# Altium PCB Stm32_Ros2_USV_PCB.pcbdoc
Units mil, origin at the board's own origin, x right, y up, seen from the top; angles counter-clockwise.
Board outline 8440 x 7060 mil, 2 copper layers (Top Layer, Bottom Layer), stack 62.206 mil thick; 19 components, 25 nets, 105 pads, 37 vias.
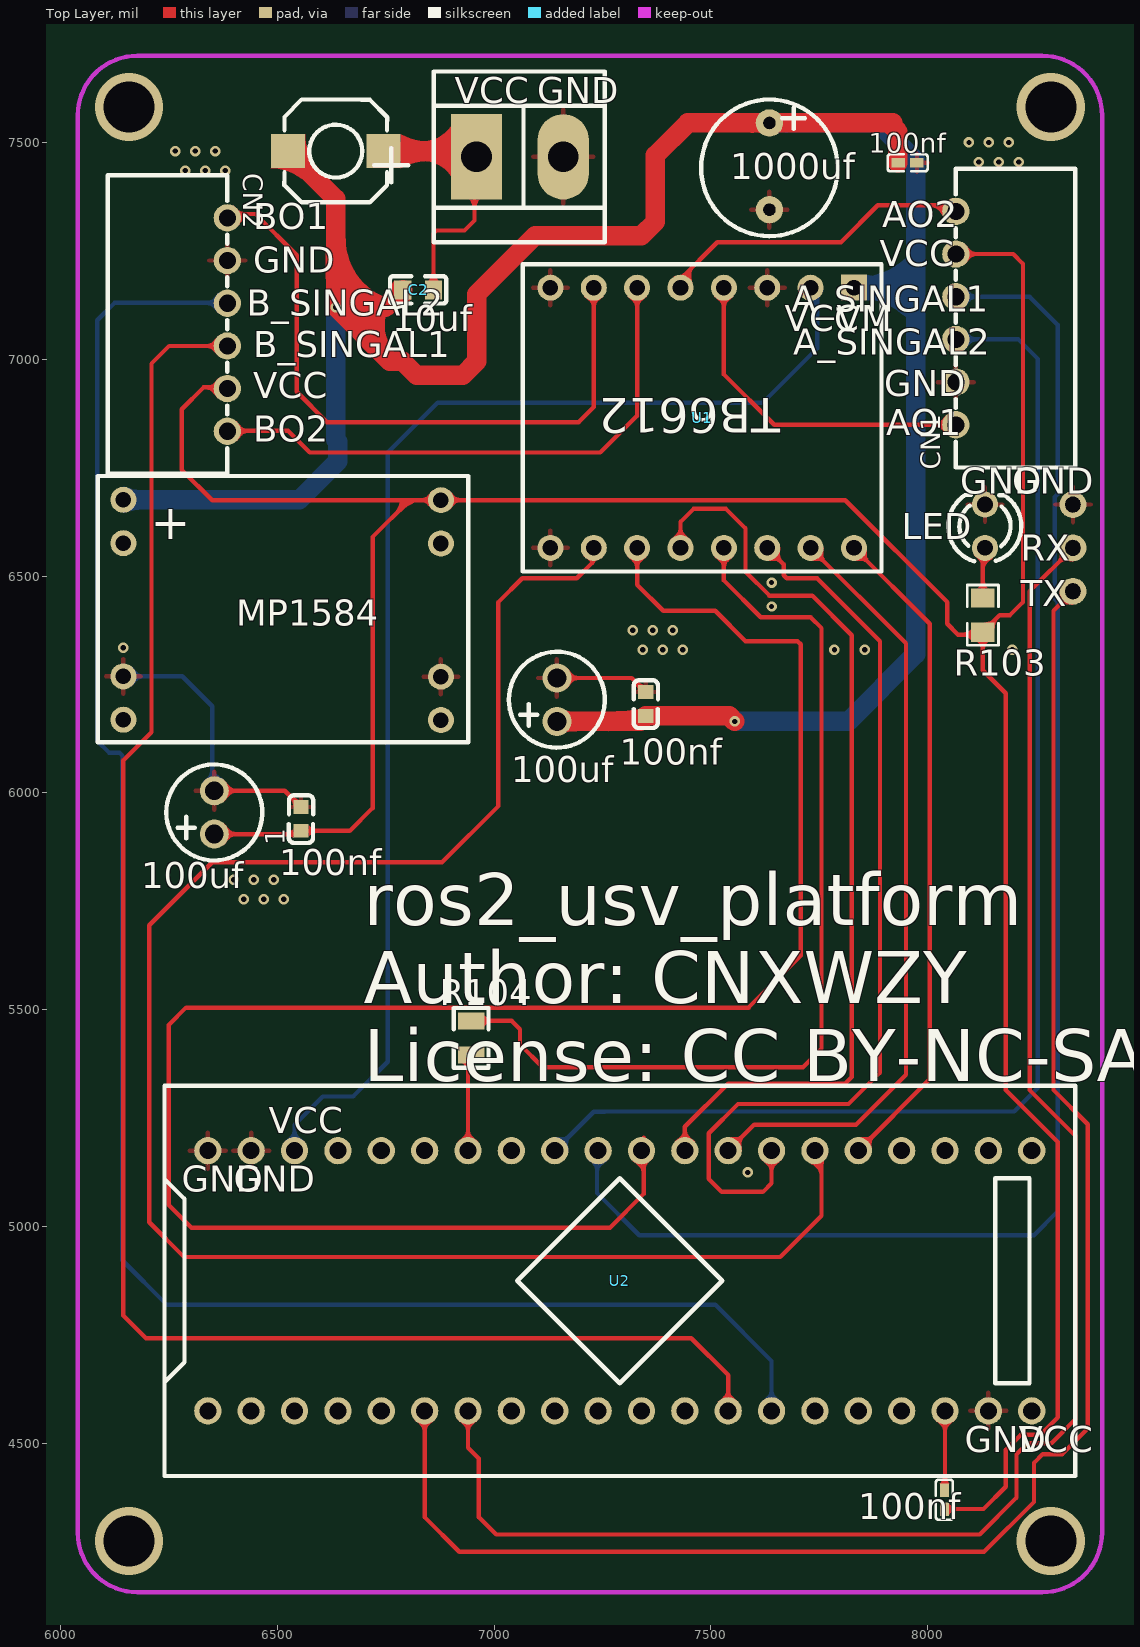
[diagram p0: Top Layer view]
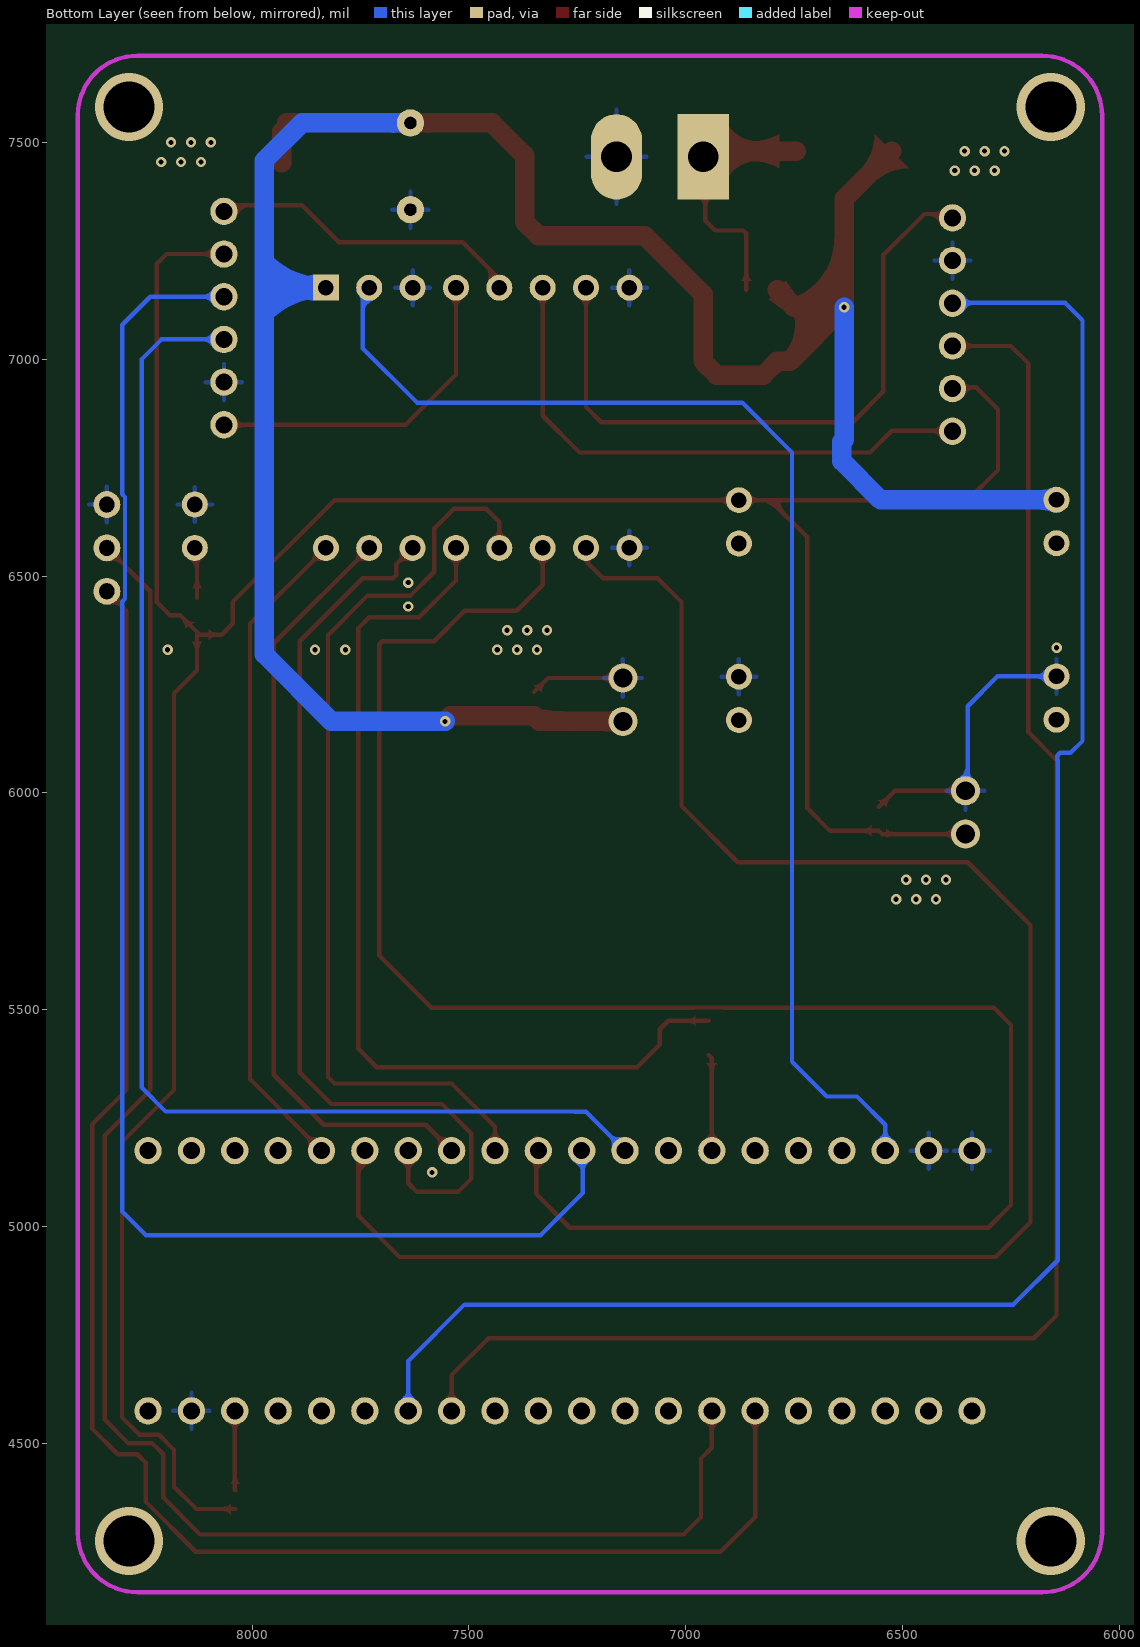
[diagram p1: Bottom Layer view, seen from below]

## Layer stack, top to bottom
Top Solder Mask Layer: solder mask 0.394, Dk 3.3
Top Layer: signal copper 1.379
Dielectric1: surface 59.449, FR4, Dk 4.5
Bottom Layer: signal copper 1.378
Bottom Solder Mask Layer: solder mask 0.394, Dk 3.3

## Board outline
11190,2750 2750,2750 2750,9810 11190,9810

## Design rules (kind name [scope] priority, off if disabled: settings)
BoardOutlineClearance copperThickness1oz [All] p0: genericclearance=10 ignorepadtopadclearanceinfootprint=FALSE except(0: Arc-SplitContinuation Track-SplitContinuation SMDPad-SplitContinuation THPad-SplitContinuation Via-SplitContinuation Fill-SplitContinuation Poly-SplitContinuation Region-SplitContinuation Text-SplitContinuation)
BoardOutlineClearance copperThickness2oz [All] p0: genericclearance=10 ignorepadtopadclearanceinfootprint=FALSE except(0: Arc-SplitContinuation Track-SplitContinuation SMDPad-SplitContinuation THPad-SplitContinuation Via-SplitContinuation Fill-SplitContinuation Poly-SplitContinuation Region-SplitContinuation Text-SplitContinuation)
BoardOutlineClearance otherClearance [All] p0: genericclearance=10 ignorepadtopadclearanceinfootprint=FALSE except(0: Arc-SplitContinuation Track-SplitContinuation SMDPad-SplitContinuation THPad-SplitContinuation Via-SplitContinuation Fill-SplitContinuation Poly-SplitContinuation Region-SplitContinuation Text-SplitContinuation)
Clearance copperThickness1oz [All] p1: gap=7 ignorepadtopadclearanceinfootprint=FALSE
Clearance copperThickness2oz [All] p1: gap=7 ignorepadtopadclearanceinfootprint=FALSE
Clearance otherClearance [All] p1: gap=7 ignorepadtopadclearanceinfootprint=FALSE
DiffPairsRouting differentialPair [All] p1: maxuncoupledlength=10 minlimit=6 maxlimit=Infinity mostfreqgap=6 toplayer_minwidth=5 toplayer_prefwidth=10 toplayer_maxwidth=100 bottomlayer_minwidth=5 bottomlayer_prefwidth=10 bottomlayer_maxwidth=100
PasteMaskExpansion pasteMaskExpansion [All] p1: expansion=0
PlaneConnect innerPlane [All] p1: planeconnectstyle=Relief reliefexpansion=20 reliefentries=4 reliefconductorwidth=10 reliefairgap=10
PolygonConnect copperRegion [All] p1: connectstyle=Relief reliefentries=4 reliefconductorwidth=10 polygonreliefangle="90 Angle" airgapwidth=10
RoutingVias viaSize [All] p1: viastyle="Through Hole" holewidth=12.0078 minholewidth=11.811 maxholewidth=248.0314 width=12.0078 minwidth=11.811 maxwidth=248.0314
SolderMaskExpansion solderMaskExpansion [All] p1: useseparateexpansions=TRUE expansion=2 expansionbottom=2
Width copperThickness1oz [All] p1: maxlimit=100 minlimit=5 preferedwidth=10
Width copperThickness2oz [All] p1: maxlimit=100 minlimit=8 preferedwidth=10

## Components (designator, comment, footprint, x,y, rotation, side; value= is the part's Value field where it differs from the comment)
1 "" C0603_7 6555,5940 r90 top locked
100nf "电容100nF" "电容100NF ±10% 16V" 7953.75,7451.69 r0 top
C2 "10UF-0603" 10UF-C0603 6825,7160 r180 top locked
CN1 "" CONN-TH_6P-P2.50_WAFER-XH2.54-6PWZ-R62 8065,7095 r90 top
CN2 "" CONN-TH_6P-P2.50_WAFER-XH2.54-6PWZ-R62 6385,7080 r270 top
U1 "TB6612FNG 最小开发板" TB6612FNG封装 7830,7165 r270 top locked
U2 "" CONN-TH_L53.3-W22.9_STM32F103C8T6-CARD 7290,4875 r0 top locked
? "" C0603_7 7350,6205 r90 top locked
? "3PIN_2.54MM_N3" 3PIN 8335,6565 r90 top locked
? "" R0805 8127.18,6410.14 r270 top locked
? "10KΩ" "电阻10KK COPY" 6947.18,5435.14 r90 top locked
? "MP1584降压模块" MP1584降压模块 6535,6420 r0 top locked
? "" 接线端子 7255,7270 r0 top locked
? "" SW-SMD_L6.0-W5.9-LS6.6 6635,7480 r180 top locked
? "" LED-TH_BD3.0-P2.54-FD 8132.18,6615.14 r90 top locked
? "100uF" 100UF电解电容 7150,6215 r90 top locked
? "100uF" 100UF电解电容 6360,5955 r90 top locked
? "1000uf" "电解电容1000UF/10V Φ3.5MM" 7635,7445 r90 top locked
? "电容100nF" "电容100NF ±10% 16V" 8040,4370 r90 top locked

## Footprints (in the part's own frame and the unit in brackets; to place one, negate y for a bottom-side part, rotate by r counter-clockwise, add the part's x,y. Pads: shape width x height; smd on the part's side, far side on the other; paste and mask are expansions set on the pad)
3PIN [mm]
  round 1.575 hole 0.889 slot 0.933 at 0 deg: 1(-2.54,0) 2(0,0) 3(2.54,0)
10UF-C0603 [mm]
  rect 1x1.1 smd: 1(-0.9,0) 2(0.9,0)
  silkscreen extent -1.65,-0.8 1.65,0.8
100UF电解电容 [mm]
  round 1.7 hole 1.1: 1(-1.27,0.127) 2(1.27,0.127)
  silkscreen extent -2.81,-2.68 2.81,2.94
C0603_7 [mm]
  rect 0.8x0.9 smd: 1(-0.7,0) 2(0.7,0)
  silkscreen extent -1.41,-0.71 1.39,0.72
CONN-TH_6P-P2.50_WAFER-XH2.54-6PWZ-R62 [mm]
  round 1.6 hole 1 copper offset 0,0: 1(-6.25,0) 2(-3.75,0) 3(-1.25,0) 4(1.25,0) 5(3.75,0) 6(6.25,0)
  silkscreen extent -8.75,-7 8.74,0
CONN-TH_L53.3-W22.9_STM32F103C8T6-CARD [mm]
  round 1.6 hole 1: 1(-24.13,-7.62) 2(-21.59,-7.62) 3(-19.05,-7.62) 4(-16.51,-7.62) 5(-13.97,-7.62) 6(-11.43,-7.62) 7(-8.89,-7.62) 8(-6.35,-7.62) 9(-3.81,-7.62) 10(-1.27,-7.62) 11(1.27,-7.62) 12(3.81,-7.62) 13(6.35,-7.62) 14(8.89,-7.62) 15(11.43,-7.62) 16(13.97,-7.62) 17(16.51,-7.62) 18(19.05,-7.62) 19(21.59,-7.62) 20(24.13,-7.62) 21(24.13,7.62) 22(21.59,7.62) 23(19.05,7.62) 24(16.51,7.62) 25(13.97,7.62) 26(11.43,7.62) 27(8.89,7.62) 28(6.35,7.62) 29(3.81,7.62) 30(1.27,7.62) 31(-1.27,7.62) 32(-3.81,7.62) 33(-6.35,7.62) 34(-8.89,7.62) 35(-11.43,7.62) 36(-13.97,7.62) 37(-16.51,7.62) 38(-19.05,7.62) 39(-21.59,7.62) 40(-24.13,7.62)
  silkscreen extent -26.67,-11.43 26.67,11.43
LED-TH_BD3.0-P2.54-FD [mil]
  round 60 hole 36: 1(-50,0) 2(50,0)
  silkscreen extent -81,-84 72,85
MP1584降压模块 [mil]
  round 60 hole 36: 1(-389.76,255.9) 2(-389.76,155.9) 3(-389.76,-151.18) 4(-389.76,-251.18) 5(342.52,255.12) 6(342.52,155.12) 7(342.52,-151.97) 8(342.52,-251.97)
  silkscreen extent -449,-303 406,311
R0805 [mm]
  rect 1.133x1.377 smd: 1(-1,0) 2(1,0)
  silkscreen extent -1.76,-0.92 1.76,0.92
SW-SMD_L6.0-W5.9-LS6.6 [mm]
  rect 2x2 smd: 1(-2.8,0) 2(2.8,0)
  silkscreen extent -3.02,-3.02 3.01,3
TB6612FNG封装 [mil]
  rect 60x60 hole 36: 1(0,0)
  round 60 hole 36: 2(0,-100) 3(0,-200) 4(0,-300) 5(0,-400) 6(0,-500) 7(0,-600) 8(0,-700) 9(600,-700) 10(600,-600) 11(600,-500) 12(600,-400) 13(600,-300) 14(600,-200) 15(600,-100) 16(600,0)
  silkscreen extent -54,-763 654,63
接线端子 [mm]
  rect 3x5 hole 1.8: 1(-7.5,5)
  oval 3x5 hole 1.8: 2(-2.42,5)
  silkscreen extent -13.5,0 0,10
"电容100NF ±10% 16V" [mm]
  rect 0.79x0.54 smd: 1(-0.545,0.035) 2(0.545,0.035)
  silkscreen extent -1.17,-0.46 1.17,0.53
"电解电容1000UF/10V Φ3.5MM" [mm]
  round 1.6 hole 0.711 slot 0.716 at 0 deg: 1(2.54,0) 2(-2.54,0)
  silkscreen extent -4.09,-4 3.91,4
"电阻10KK COPY" [mm]
  rect 1x1.55 smd: 1(-1,0) 2(1,0)
  silkscreen extent -1.75,-1.02 1.75,1.02

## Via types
v1: diameter 24, hole 12.01, Top Layer to Bottom Layer, 31 vias
v2: diameter 157.48, hole 118.11, Top Layer to Bottom Layer, 4 vias
v3: diameter 24.02, hole 12.01, Top Layer to Bottom Layer, 2 vias

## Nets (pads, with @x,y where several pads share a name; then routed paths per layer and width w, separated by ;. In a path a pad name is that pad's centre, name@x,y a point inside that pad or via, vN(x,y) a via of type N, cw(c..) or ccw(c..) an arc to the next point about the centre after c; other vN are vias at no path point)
$1N61: ?.1@6745.24,7480.01 ?.1@6959.72,7466.85 C2.1 | length 605.7
  Top Layer w10: C2.1 6860.44,7290 6867.51,7297.07 6932.07,7297.07 6955,7320 6955,7462.13 ?.1@6959.72,7466.85
  Top Layer w45: ?.1@6745.24,7480.01 6946.57,7480.01 ?.1@6959.72,7466.85
$1N63: ?.1@8127.18,6449.51 ?.1@8132.18,6565.14 | length 117.7
  Top Layer w10: ?.1@8127.18,6449.51 8127.18,6560.14 ?.1@8132.18,6565.14
$1N81: ?.2@6947.18,5474.51 U1.13 | length 2205.8
  Top Layer w10: ?.2@6947.18,5474.51 7040.49,5474.51 7060,5455 7060,5420 7112.5,5367.5 7712.5,5367.5 7755,5410 7755,6380 7730,6405 7615,6405 7530,6490 U1.13
$1N88: ?.2@8038.63,4391.47 U2.18 | length 184.1
  Top Layer w10: ?.2@8038.63,4391.47 8040,4392.84 U2.18
A_SINGAL1: CN1.4 U2.31 | length 3535.5
  Bottom Layer w10: U2.31 7237.5,5172.5 7237.5,5077.5 7335,4980 8245,4980 8299.61,5034.61 8299.61,6441.01 8293.01,6447.61 8293.01,6682.39 8299.61,6688.99 8299.61,7079.61 8235,7144.22 CN1.4
A_SINGAL2: CN1.3 U2.32 | length 3062.9
  Bottom Layer w10: U2.32 7230,5265 7255,5265 7255.4,5265.4 8199.6,5265.4 8254.19,5320 8254.19,7000.81 8209.2,7045.8 CN1.3
AIN1: U1.14 U2.27 | length 2157.4
  Top Layer w10: U1.14 7667.93,6527.07 7667.93,6502.07 7675,6495 7745,6495 7890,6350 7890,5355 7817.5,5282.5 7562.5,5282.5 7495,5215 7495,5110 7525,5080 7620,5080 7640,5100 U2.27
AIN2: U1.15 U2.28 | length 1788.6
  Top Layer w10: U2.28 7599.72,5234.72 7834.72,5234.72 7950,5350 7950,6345 U1.15
AO1: CN1.1 U1.4 | length 783.1
  Top Layer w10: U1.4 7530,6965 7646.06,6848.94 CN1.1
AO2: CN1.6 U1.5 | length 731.2
  Top Layer w10: U1.5 7430,7185 7515,7270 7800,7270 7885,7355 8051.06,7355 CN1.6@8065,7341.06
B_SINGAL1: CN2.4 U2.13 | length 3948.3
  Top Layer w10: CN2.4 6250.78,7030.78 6210,6990 6210,6140 6145,6075 6145,4795 6197.5,4742.5 7455,4742.5 7540,4657.5 U2.13
B_SINGAL2: CN2.3 U2.14 | length 4231.9
  Bottom Layer w10: CN2.3 6384.2,7130 6125,7130 6085,7090 6085,6120 6112.08,6092.92 6136.28,6092.92 6143.35,6085.85 6143.35,6075.85 6142.5,6075 6142.5,4922.5 6245,4820 7510,4820 7640,4690 U2.14
BIN1: U1.12 U2.29 | length 2153
  Top Layer w10: U1.12 7430,6625 7460,6655 7535,6655 7580,6610 7580,6510 7635,6455 7733.77,6455 7825,6363.77 7825,5345 7810,5330 7540,5330 7440,5230 U2.29
BIN2: U1.11 U2.30 | length 4454.1
  Top Layer w10: U1.11 7330,6480 7390,6420 7510,6420 7580,6350 7700,6350 7707.07,6342.93 7707.07,5625 7587.07,5505 6982.42,5505 6982.24,5505.18 6912.11,5505.18 6911.94,5505 6290,5505 6250,5465 6250,5050 6302.5,4997.5 7267.5,4997.5 7345,5075 U2.30@7345,5205
BO1: CN2.1 U1.7 | length 1492.8
  Top Layer w10: CN2.1@6410.06,7335.15 6449.85,7335.15 6545,7240 6545,6925 6615,6855 7195,6855 7230,6890 U1.7
BO2: CN2.6 U1.6 | length 1270.9
  Top Layer w10: CN2.6@6410.06,6835.15 6524.85,6835.15 6575,6785 7245,6785 7330,6870 U1.6
GND: 1.2 100nf.2 ?.2@6355,6005 ?.2@7145,6265 ?.2@7159.72,7466.85 ?.2@7350,6232.56 ?.2@7635,7345 ?.2@8132.18,6665.14 ?.3 ?.7 CN1.2 CN2.2 U1.3 U1.8 U1.9 U2.19 U2.39 U2.40 | length 864.3
  Top Layer w10: ?.2@6355,6005 6517.56,6005 1.2 ; ?.2@7145,6265 7317.56,6265 ?.2@7350,6232.56
  Bottom Layer w10: ?.3@6145.24,6268.82 6281.18,6268.82 6350,6200 6350,6010 ?.2@6355,6005
  other v1: 7585,5125 6423,5755 6469,5755 6515,5755 6400,5800 6446,5800 6492,5800 7343,6330 7389,6330 7435,6330 7785,6330 7855,6330 8195,6330 6145,6335 7320,6375 7366,6375 7412,6375 7640,6430 7640,6485 6288,7435 6334,7435 6380,7435 8118,7455 8164,7455 8210,7455 6265,7480 6311,7480 6357,7480 8095,7500 8141,7500 8187,7500
PWMA: U1.16 U2.25 | length 1530.8
  Top Layer w10: U1.16 8005,6390 8005,5340 U2.25
PWMB: U1.10 U2.26 | length 4142.5
  Top Layer w10: U1.10 7227.07,6562.07 7227.07,6531.09 7190.98,6495 7065,6495 7010,6440 7010,5970 6880,5840 6350,5840 6205,5695 6205,5010 6285,4930 7660,4930 7755,5025 7755,5160 U2.26
RX: ?.2@8335,6565 U2.7 | length 3910.2
  Top Layer w10: U2.7 6940,4490 6965,4465 6965,4330 7005,4290 8120,4290 8205,4375 8205,4475 8230,4500 8285,4500 8340,4555 8340,5210 8235,5315 8235,6465 ?.2@8335,6565
STBY: ?.1@6947.18,5395.77 U2.34 | length 223.7
  Top Layer w10: U2.34 6940,5388.6 ?.1@6947.18,5395.77
TX: ?.1@8335,6465 U2.6 | length 3959.9
  Top Layer w10: U2.6 6840,4330 6920,4250 8130,4250 8245,4365 8245,4455 8265,4475 8310,4475 8369.04,4534.04 8369.04,5235.96 8290,5315 8290,6420 ?.1@8335,6465
VCC+3.3V: U1.2 U2.38 | length 2975.7
  Bottom Layer w10: U2.38 6540,5235 6605,5300 6675,5300 6755,5380 6755,6785 6870,6900 7620,6900 7745,7025 7745,7150 U1.2
VCC+5V: 1.1 ?.1@6355,5905 ?.1@8038.63,4348.55 ?.2@8127.18,6370.77 ?.5 CN1.5 CN2.5 | length 6759.1
  Top Layer w10: ?.1@6355,5905 6547.56,5905 1.1 6667.44,5912.44 6720,5965 6720,6590 6805,6675 ; CN2.5@6359.94,6935.15 6330.15,6935.15 6280,6885 6280,6745 6350,6675 6805,6675 ; ?.1@8038.63,4348.55 8128.55,4348.55 8180,4400 8180,4485 8215,4520 8260,4520 8300,4560 8300,5195 8180,5315 8180,6230 8127.18,6282.82 ?.2@8127.18,6370.77 ; CN1.5 8197.36,7242.64 8220,7220 8220,6440 8190,6410 8166.41,6410 ?.2@8127.18,6370.77 ; 6805,6675 6877.4,6675 ?.5 7809.88,6675.12 8045,6440 8045,6390 8070,6365 8121.41,6365 ?.2@8127.18,6370.77
VCC+12V: 100nf.1 ?.1@6145.24,6675.9 ?.1@7145,6165 ?.1@7350,6177.44 ?.1@7635,7545 ?.2@6524.76,7480.01 C2.2 U1.1 | length 5892.9
  Top Layer w45: ?.2@6524.76,7480.01 6635,7369.77 v3(6635,7120) ; C2.2 6749.56,7120 v3(6635,7120) ; ?.1@7145,6165 7337.56,6165 7350,6177.44 7542.56,6177.44 v3(7555,6165) ; 7920,7545 7911.03,7545 ; 100nf.1@7931.18,7453.06 7931.18,7524.85 7911.03,7545 ; v3(6635,7120) 6760,6995 6789.56,6995 6821.38,6963.18 6928.18,6963.18 6960,6995 6960,7150 7095,7285 7340,7285 7371.82,7316.82 7371.82,7470 7446.82,7545 7635,7545 7911.03,7545
  Bottom Layer w45: ?.1@6145.24,6675.9 6550.9,6675.9 6640,6765 6640,6810 6635,6815 v3(6635,7120) ; v3(7555,6165) 7817.06,6165 7972.06,6320 7972.06,7167.19 ; ?.1@7635,7545 7885,7545 7972.06,7457.94 7972.06,7167.19 ; U1.1 7969.87,7165 7972.06,7167.19
pads on no net: ?.2@6145.24,6575.9 ?.4 ?.6 ?.8 U2.1 U2.2 U2.3 U2.4 U2.5 U2.8 U2.9 U2.10 U2.11 U2.12 U2.15 U2.16 U2.17 U2.20 U2.21 U2.22 U2.23 U2.24 U2.33 U2.35 U2.36 U2.37
copper on no net:
  other v2: 6158.11,4274.79 8284.09,4274.8 6158.11,7581.89 8284.09,7581.89

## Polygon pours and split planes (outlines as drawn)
GND on Top Layer (solid, remove dead copper, pour order 0): 5595,8120 9140,8120 9140,3935 5595,3935
GND on Bottom Layer (solid, remove dead copper, pour order 4): 3000,9560 10940,9560 10940,3000 3000,3000

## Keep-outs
Board Outline Layer:
  lines w10: 6040,4294.49 ccw(c6177.8,4294.49) 6177.8,4156.69 8264.41,4156.69 ccw(c8264.41,4294.49) 8402.2,4294.49 8402.2,7562.2 ccw(c8264.41,7562.2) 8264.41,7700 6177.8,7700 ccw(c6177.8,7562.2) 6040,7562.2 6040,4294.49

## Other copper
Top Layer:
  region net GND: 6531.98,5983.51 6541.02,5988.61 ccw(c6556.93,6009.82) 6556.93,5983.31 6537.28,5967.6 ccw(c6510.77,5967.6)
  region net VCC+5V: 6522.28,5900 6522.28,5910 ccw(c6522.28,5928.75) 6537.28,5917.5 6537.28,5896.69 ccw(c6522.28,5864.34)
  region net VCC+5V: 6587.72,5917.44 6587.72,5907.44 ccw(c6587.72,5888.69) 6572.72,5899.94 6572.72,5924.94 ccw(c6587.72,5936.19)
  region net GND: 7326.98,6248.51 7336.02,6253.61 ccw(c7351.93,6274.82) 7351.93,6248.31 7332.28,6232.6 ccw(c7305.77,6232.6)
  region net VCC+12V: 7264.78,6142.5 7264.78,6187.5 ccw(c7264.78,6590.86) 7332.28,6193.19 7332.28,6161.69 ccw(c7332.28,6033.39)
  region net $1N61: 6855.44,7196.65 6865.44,7196.65 ccw(c6884.19,7196.65) 6872.94,7181.65 6847.94,7181.65 ccw(c6836.69,7196.65)
  region net VCC+12V: 6765.47,7104.09 6733.66,7135.91 ccw(c6554.81,7314.75) 6769.88,7181.65 6809.25,7138.35 ccw(c6927.77,6941.79)
  region net TX: 8308.69,6431.62 8301.62,6438.69 8302.65,6439.96 8303.47,6441.43 8304.09,6443.09 8304.54,6444.9 8304.99,6448.83 8305.01,6452.99 8304.75,6457.13 8304.39,6461 8304.1,6464.35 8304.06,6466.94 8336.94,6434.06 8334.35,6434.1 8331,6434.39 8327.13,6434.75 8322.99,6435.01 8318.83,6434.99 8314.9,6434.54 8313.09,6434.09 8311.43,6433.47 8309.96,6432.65
  region net RX: 8308.69,6531.62 8301.62,6538.69 8302.65,6539.96 8303.47,6541.43 8304.09,6543.09 8304.54,6544.9 8304.99,6548.83 8305.01,6552.99 8304.75,6557.13 8304.39,6561 8304.1,6564.35 8304.06,6566.94 8336.94,6534.06 8334.35,6534.1 8331,6534.39 8327.13,6534.75 8322.99,6535.01 8318.83,6534.99 8314.9,6534.54 8313.09,6534.09 8311.43,6533.47 8309.96,6532.65
  region net VCC+5V: 8085.07,6360 8085.07,6370 ccw(c8085.07,6388.75) 8100.07,6377.5 8100.07,6352.5 ccw(c8085.07,6341.25)
  region net VCC+5V: 8132.18,6333.48 8122.18,6333.48 ccw(c8103.43,6333.48) 8114.68,6348.48 8139.68,6348.48 ccw(c8150.93,6333.48)
  region net VCC+5V: 8147.7,6398.37 8159.59,6396.11 ccw(c8180.8,6380.2) 8154.28,6380.2 8131.79,6393.06 ccw(c8131.79,6419.58)
  region net $1N63: 8122.18,6486.8 8132.18,6486.8 ccw(c8150.93,6486.8) 8139.68,6471.8 8114.68,6471.8 ccw(c8103.43,6486.8)
  region net $1N81: 6992.69,5479.51 6992.69,5469.51 ccw(c6992.69,5450.76) 6977.69,5462.01 6977.69,5487.01 ccw(c6992.69,5498.26)
  region net STBY: 6945,5361.08 6935,5361.08 ccw(c6916.25,5361.08) 6927.5,5376.08 6952.5,5376.08 ccw(c6963.75,5361.08)
  region net AO1: 7535,7124.16 7525,7124.16 7524.84,7125.73 7524.4,7127.3 7523.69,7128.86 7522.77,7130.41 7520.42,7133.41 7517.61,7136.27 7514.63,7138.93 7511.76,7141.33 7509.29,7143.42 7507.5,7145.16 7552.5,7145.16 7550.71,7143.42 7548.24,7141.33 7545.37,7138.93 7542.39,7136.27 7539.58,7133.41 7537.23,7130.41 7536.31,7128.86 7535.6,7127.3 7535.16,7125.73
  region net AO2: 7436.19,7198.26 7458.26,7206.19 7457.24,7204.94 7456.41,7203.46 7455.76,7201.78 7455.27,7199.93 7454.92,7197.95 7454.71,7195.87 7454.65,7191.56 7454.98,7187.28 7455.6,7183.32 7456.4,7179.95 7457.29,7177.46 7414.23,7190.52 7416.07,7191.31 7418.5,7191.93 7424.47,7193.08 7427.67,7193.85 7430.81,7194.89 7433.7,7196.32 7435.01,7197.22
  region net BO2: 7335,7124.16 7325,7124.16 7324.84,7125.73 7324.4,7127.3 7323.69,7128.86 7322.77,7130.41 7320.42,7133.41 7317.61,7136.27 7314.63,7138.93 7311.76,7141.33 7309.29,7143.42 7307.5,7145.16 7352.5,7145.16 7350.71,7143.42 7348.24,7141.33 7345.37,7138.93 7342.39,7136.27 7339.58,7133.41 7337.23,7130.41 7336.31,7128.86 7335.6,7127.3 7335.16,7125.73
  region net BO1: 7235,7124.16 7225,7124.16 7224.84,7125.73 7224.4,7127.3 7223.69,7128.86 7222.77,7130.41 7220.42,7133.41 7217.61,7136.27 7214.63,7138.93 7211.76,7141.33 7209.29,7143.42 7207.5,7145.16 7252.5,7145.16 7250.71,7143.42 7248.24,7141.33 7245.37,7138.93 7242.39,7136.27 7239.58,7133.41 7237.23,7130.41 7236.31,7128.86 7235.6,7127.3 7235.16,7125.73
  region net PWMB: 7232.07,6531.09 7222.07,6531.09 7221.92,6532.31 7221.48,6533.51 7220.79,6534.7 7219.89,6535.88 7217.6,6538.15 7214.89,6540.31 7209.38,6544.23 7207.15,6545.93 7205.67,6547.45 7250.46,6543.06 7248.74,6541.88 7246.23,6540.6 7240.06,6537.74 7237.04,6536.19 7234.49,6534.56 7233.49,6533.71 7232.73,6532.85 7232.24,6531.98
  region net BIN2: 7335,6524.16 7325,6524.16 7324.84,6525.73 7324.4,6527.3 7323.69,6528.86 7322.77,6530.41 7320.42,6533.41 7317.61,6536.27 7314.63,6538.93 7311.76,6541.33 7309.29,6543.42 7307.5,6545.16 7352.5,6545.16 7350.71,6543.42 7348.24,6541.33 7345.37,6538.93 7342.39,6536.27 7339.58,6533.41 7337.23,6530.41 7336.31,6528.86 7335.6,6527.3 7335.16,6525.73
  region net BIN1: 7425,6605.84 7435,6605.84 7435.16,6604.27 7435.6,6602.7 7436.31,6601.14 7437.23,6599.59 7439.58,6596.59 7442.39,6593.73 7445.37,6591.07 7448.24,6588.67 7450.71,6586.58 7452.5,6584.84 7407.5,6584.84 7409.29,6586.58 7411.76,6588.67 7414.63,6591.07 7417.61,6593.73 7420.42,6596.59 7422.77,6599.59 7423.69,6601.14 7424.4,6602.7 7424.84,6604.27
  region net $1N81: 7535,6524.16 7525,6524.16 7524.84,6525.73 7524.4,6527.3 7523.69,6528.86 7522.77,6530.41 7520.42,6533.41 7517.61,6536.27 7514.63,6538.93 7511.76,6541.33 7509.29,6543.42 7507.5,6545.16 7552.5,6545.16 7550.71,6543.42 7548.24,6541.33 7545.37,6538.93 7542.39,6536.27 7539.58,6533.41 7537.23,6530.41 7536.31,6528.86 7535.6,6527.3 7535.16,6525.73
  region net AIN1: 7662.42,6539.66 7655.34,6532.58 7654.12,6533.59 7652.69,6534.38 7651.09,6534.99 7649.35,6535.43 7645.56,6535.89 7641.55,6535.92 7637.57,6535.69 7633.84,6535.36 7630.61,6535.1 7628.12,6535.06 7659.94,6566.88 7659.9,6564.39 7659.64,6561.16 7659.31,6557.43 7659.08,6553.45 7659.11,6549.44 7659.57,6545.65 7660.01,6543.91 7660.62,6542.31 7661.41,6540.88
  region net AIN2: 7762.42,6539.66 7755.34,6532.58 7754.12,6533.59 7752.69,6534.38 7751.09,6534.99 7749.35,6535.43 7745.56,6535.89 7741.55,6535.92 7737.57,6535.69 7733.84,6535.36 7730.61,6535.1 7728.12,6535.06 7759.94,6566.88 7759.9,6564.39 7759.64,6561.16 7759.31,6557.43 7759.08,6553.45 7759.11,6549.44 7759.57,6545.65 7760.01,6543.91 7760.62,6542.31 7761.41,6540.88
  region net PWMA: 7862.42,6539.66 7855.34,6532.58 7854.12,6533.59 7852.69,6534.38 7851.09,6534.99 7849.35,6535.43 7845.56,6535.89 7841.55,6535.92 7837.57,6535.69 7833.84,6535.36 7830.61,6535.1 7828.12,6535.06 7859.94,6566.88 7859.9,6564.39 7859.64,6561.16 7859.31,6557.43 7859.08,6553.45 7859.11,6549.44 7859.57,6545.65 7860.01,6543.91 7860.62,6542.31 7861.41,6540.88
  region net TX: 6845,4532.12 6835,4532.12 6834.83,4533.77 6834.36,4535.42 6833.61,4537.06 6832.63,4538.68 6831.45,4540.27 6830.12,4541.83 6827.12,4544.83 6823.95,4547.62 6820.9,4550.14 6818.28,4552.34 6816.38,4554.17 6863.62,4554.17 6861.73,4552.34 6859.1,4550.14 6856.05,4547.62 6852.88,4544.83 6849.89,4541.83 6848.55,4540.27 6847.37,4538.68 6846.39,4537.06 6845.65,4535.42 6845.17,4533.77
  region net RX: 6945,4532.12 6935,4532.12 6934.83,4533.77 6934.36,4535.42 6933.61,4537.06 6932.63,4538.68 6931.45,4540.27 6930.12,4541.83 6927.12,4544.83 6923.95,4547.62 6920.9,4550.14 6918.28,4552.34 6916.38,4554.17 6963.62,4554.17 6961.73,4552.34 6959.1,4550.14 6956.05,4547.62 6952.88,4544.83 6949.89,4541.83 6948.55,4540.27 6947.37,4538.68 6946.39,4537.06 6945.65,4535.42 6945.17,4533.77
  region net B_SINGAL1: 7535,4617.88 7545,4617.88 7545.17,4616.23 7545.65,4614.58 7546.39,4612.94 7547.37,4611.32 7548.55,4609.73 7549.89,4608.17 7552.88,4605.17 7556.05,4602.39 7559.1,4599.86 7561.73,4597.66 7563.62,4595.83 7516.38,4595.83 7518.28,4597.66 7520.9,4599.86 7523.95,4602.39 7527.12,4605.17 7530.12,4608.17 7531.45,4609.73 7532.63,4611.32 7533.61,4612.94 7534.36,4614.58 7534.83,4616.23
  region net $1N88: 8045,4532.12 8035,4532.12 8034.83,4533.77 8034.36,4535.42 8033.61,4537.06 8032.63,4538.68 8031.45,4540.27 8030.12,4541.83 8027.12,4544.83 8023.95,4547.62 8020.9,4550.14 8018.28,4552.34 8016.38,4554.17 8063.62,4554.17 8061.73,4552.34 8059.1,4550.14 8056.05,4547.62 8052.88,4544.83 8049.89,4541.83 8048.55,4540.27 8047.37,4538.68 8046.39,4537.06 8045.65,4535.42 8045.17,4533.77
  region net PWMA: 7866.79,5208.86 7873.86,5201.79 7872.81,5200.5 7871.98,5199 7871.35,5197.31 7870.9,5195.47 7870.61,5193.51 7870.45,5191.47 7870.44,5187.23 7870.72,5183.01 7871.09,5179.08 7871.39,5175.66 7871.44,5173.03 7838.03,5206.44 7840.66,5206.39 7844.08,5206.09 7848.02,5205.72 7852.23,5205.44 7856.47,5205.45 7858.51,5205.6 7860.47,5205.9 7862.31,5206.35 7864,5206.98 7865.5,5207.81
  region net PWMB: 7760,5145.88 7750,5123.39 7749.83,5125.06 7749.34,5126.78 7748.56,5128.52 7747.54,5130.26 7746.31,5131.99 7744.91,5133.69 7741.71,5136.93 7738.25,5139.86 7734.81,5142.35 7731.68,5144.25 7729.15,5145.43 7770.69,5167.93 7769.92,5165.97 7768.56,5163.71 7764.93,5158.42 7763.09,5155.48 7761.52,5152.38 7760.89,5150.78 7760.41,5149.17 7760.11,5147.53
  region net AIN1: 7645,5132.12 7635,5132.12 7634.83,5133.77 7634.36,5135.42 7633.61,5137.06 7632.63,5138.68 7631.45,5140.27 7630.12,5141.83 7627.12,5144.83 7623.95,5147.62 7620.9,5150.14 7618.28,5152.34 7616.38,5154.17 7663.62,5154.17 7661.73,5152.34 7659.1,5150.14 7656.05,5147.62 7652.88,5144.83 7649.89,5141.83 7648.55,5140.27 7647.37,5138.68 7646.39,5137.06 7645.65,5135.42 7645.17,5133.77
  region net AIN2: 7566.79,5208.86 7573.86,5201.79 7572.81,5200.5 7571.98,5199 7571.35,5197.31 7570.9,5195.47 7570.61,5193.51 7570.45,5191.47 7570.44,5187.23 7570.72,5183.01 7571.09,5179.08 7571.39,5175.66 7571.44,5173.03 7538.03,5206.44 7540.66,5206.39 7544.08,5206.09 7548.02,5205.72 7552.23,5205.44 7556.47,5205.45 7558.51,5205.6 7560.47,5205.9 7562.31,5206.35 7564,5206.98 7565.5,5207.81
  region net BIN1: 7435,5217.88 7445,5217.88 7445.17,5216.23 7445.65,5214.58 7446.39,5212.94 7447.37,5211.32 7448.55,5209.73 7449.89,5208.17 7452.88,5205.17 7456.05,5202.39 7459.1,5199.86 7461.73,5197.66 7463.62,5195.83 7416.38,5195.83 7418.28,5197.66 7420.9,5199.86 7423.95,5202.39 7427.12,5205.17 7430.12,5208.17 7431.45,5209.73 7432.63,5211.32 7433.61,5212.94 7434.36,5214.58 7434.83,5216.23
  region net BIN2: 7350,5136.13 7340,5128.64 7339.83,5130.3 7339.33,5131.96 7338.55,5133.62 7337.52,5135.27 7336.28,5136.9 7334.88,5138.49 7331.72,5141.55 7328.34,5144.37 7325.05,5146.88 7319.99,5150.68 7366.63,5158.18 7365.07,5156.25 7362.79,5154.01 7357.21,5148.71 7354.48,5145.75 7352.18,5142.64 7351.28,5141.04 7350.59,5139.42 7350.15,5137.78
  region net STBY: 6935,5217.88 6945,5217.88 6945.17,5216.23 6945.65,5214.58 6946.39,5212.94 6947.37,5211.32 6948.55,5209.73 6949.89,5208.17 6952.88,5205.17 6956.05,5202.39 6959.1,5199.86 6961.73,5197.66 6963.62,5195.83 6916.38,5195.83 6918.28,5197.66 6920.9,5199.86 6923.95,5202.39 6927.12,5205.17 6930.12,5208.17 6931.45,5209.73 6932.63,5211.32 6933.61,5212.94 6934.36,5214.58 6934.83,5216.23
  region net VCC+5V: 6836.76,6670 6836.59,6680 6838.16,6680.16 6839.73,6680.6 6841.29,6681.31 6842.84,6682.23 6845.84,6684.59 6848.7,6687.41 6851.36,6690.39 6853.76,6693.27 6855.86,6695.74 6857.59,6697.54 6857.76,6652.54 6856.02,6654.32 6853.93,6656.79 6851.53,6659.64 6848.87,6662.62 6846.01,6665.42 6843.01,6667.78 6841.47,6668.7 6839.91,6669.4 6838.34,6669.84
  region net VCC+5V: 6918.36,6680.12 6918.36,6670.12 6916.79,6669.96 6915.22,6669.51 6913.66,6668.81 6912.11,6667.89 6909.11,6665.53 6906.25,6662.72 6903.59,6659.74 6901.19,6656.88 6899.1,6654.41 6897.36,6652.62 6897.36,6697.62 6899.1,6695.83 6901.19,6693.36 6903.59,6690.49 6906.25,6687.51 6909.11,6684.7 6912.11,6682.34 6913.66,6681.42 6915.22,6680.72 6916.79,6680.27
  region net $1N61: 6960,7353.43 6950,7353.43 ccw(c6931.25,7353.43) 6942.5,7368.43 6950,7368.43 6960,7368.43 6967.5,7368.43 ccw(c6978.75,7353.43)
  region net $1N61: 6833.17,7457.51 6833.17,7502.51 ccw(c6833.17,7586.88) 6900.67,7536.26 6900.67,7502.51 6900.67,7457.51 6900.67,7423.76 ccw(c6833.17,7373.13)
  region net VCC+12V: 6588.4,7448.19 6556.58,7416.37 ccw(c6485.39,7324.09) 6485.39,7440.64 6564.13,7519.38 ccw(c6680.68,7519.38)
  region net $1N61: 6852.11,7502.51 6852.11,7457.51 ccw(c6852.11,7314.03) 6784.61,7440.64 6784.61,7519.38 ccw(c6852.11,7645.98)
  region net $1N63: 8132.18,6520.82 8122.18,6528.32 8122.03,6529.89 8121.62,6531.46 8120.98,6533 8120.14,6534.52 8118,6537.49 8115.46,6540.31 8110.26,6545.35 8108.14,6547.49 8106.68,6549.32 8151.05,6541.82 8146.25,6538.22 8143.15,6535.83 8139.97,6533.14 8136.99,6530.22 8135.67,6528.7 8134.51,6527.15 8133.54,6525.58 8132.81,6523.99 8132.34,6522.4
  region net GND: 7190.56,6270 7190.56,6260 7188.8,6259.82 7187.05,6259.3 7185.32,6258.5 7183.6,6257.43 7181.91,6256.16 7180.25,6254.72 7177.07,6251.48 7174.11,6248.06 7171.43,6244.76 7169.09,6241.94 7167.13,6239.9 7167.13,6290.1 7169.09,6288.06 7171.43,6285.24 7174.11,6281.94 7177.07,6278.52 7180.25,6275.28 7181.91,6273.84 7183.6,6272.57 7185.32,6271.5 7187.05,6270.7 7188.8,6270.18
  region net VCC+12V: 7190.56,6187.5 7190.56,6142.5 7183.44,6142.53 7176.66,6142.37 7173.63,6142.09 7170.97,6141.62 7168.77,6140.91 7167.88,6140.44 7167.13,6139.9 7167.13,6190.1 7167.88,6189.56 7168.77,6189.09 7170.97,6188.38 7173.63,6187.91 7176.66,6187.63 7183.44,6187.47
  region net GND: 6400.56,6010 6400.56,6000 6398.8,5999.82 6397.05,5999.3 6395.32,5998.5 6393.6,5997.43 6391.91,5996.16 6390.25,5994.72 6387.07,5991.48 6384.11,5988.06 6381.43,5984.76 6379.09,5981.94 6377.13,5979.9 6377.13,6030.1 6379.09,6028.06 6381.43,6025.24 6384.11,6021.94 6387.07,6018.52 6390.25,6015.28 6391.91,6013.84 6393.6,6012.57 6395.32,6011.5 6397.05,6010.7 6398.8,6010.18
  region net VCC+5V: 6400.56,5910 6400.56,5900 6398.8,5899.82 6397.05,5899.3 6395.32,5898.5 6393.6,5897.43 6391.91,5896.16 6390.25,5894.72 6387.07,5891.48 6384.11,5888.06 6381.43,5884.76 6379.09,5881.94 6377.13,5879.9 6377.13,5930.1 6379.09,5928.06 6381.43,5925.24 6384.11,5921.94 6387.07,5918.52 6390.25,5915.28 6391.91,5913.84 6393.6,5912.57 6395.32,5911.5 6397.05,5910.7 6398.8,5910.18
  region net VCC+12V: 7592.12,7522.5 7592.12,7567.5 7598.82,7567.26 7605.21,7566.97 7608.06,7566.98 7610.57,7567.21 7612.63,7567.74 7613.47,7568.13 7614.17,7568.62 7614.17,7521.38 7613.47,7521.87 7612.63,7522.26 7610.57,7522.79 7608.06,7523.02 7605.21,7523.03 7598.82,7522.74
  region net $1N88: 8035,4422.02 8045,4422.02 ccw(c8073.55,4422.02) 8049.26,4407.02 8028,4407.02 ccw(c8015.43,4422.02)
  region net VCC+5V: 8064.26,4353.55 8064.26,4343.55 ccw(c8064.26,4324.8) 8049.26,4336.05 8049.26,4361.05 ccw(c8064.26,4372.3)
  region net AO2: 8013.81,7350 8034.73,7360 8036.38,7360.11 8038.01,7360.44 8039.63,7360.95 8041.22,7361.61 8044.32,7363.28 8047.26,7365.24 8052.55,7369.12 8054.82,7370.59 8056.78,7371.46 8035.86,7329.1 8034.61,7331.61 8032.68,7334.74 8030.2,7338.18 8027.28,7341.66 8024.06,7344.87 8022.37,7346.28 8020.66,7347.52 8018.93,7348.55 8017.2,7349.33 8015.49,7349.83
  region net AO1: 8022.12,6843.94 8022.12,6853.94 8023.77,6854.11 8025.42,6854.59 8027.06,6855.34 8028.68,6856.32 8030.27,6857.5 8031.83,6858.83 8034.83,6861.82 8037.61,6865 8040.14,6868.05 8042.34,6870.67 8044.17,6872.57 8044.17,6825.32 8042.34,6827.22 8040.14,6829.84 8037.61,6832.89 8034.83,6836.07 8031.83,6839.06 8030.27,6840.39 8028.68,6841.57 8027.06,6842.55 8025.42,6843.3 8023.77,6843.78
  region net VCC+5V: 8107.88,7247.64 8107.88,7237.64 8106.23,7237.47 8104.58,7236.99 8102.94,7236.24 8101.32,7235.26 8099.73,7234.08 8098.17,7232.75 8095.17,7229.76 8092.39,7226.58 8089.86,7223.53 8087.66,7220.91 8085.83,7219.01 8085.83,7266.26 8087.66,7264.36 8089.86,7261.74 8092.39,7258.69 8095.17,7255.51 8098.17,7252.52 8099.73,7251.19 8101.32,7250.01 8102.94,7249.03 8104.58,7248.28 8106.23,7247.8
  region net BO2: 6426.96,6840.15 6428.77,6830.15 6427.12,6829.99 6425.47,6829.5 6423.82,6828.74 6422.2,6827.75 6420.6,6826.55 6419.03,6825.2 6416.02,6822.15 6413.23,6818.92 6410.71,6815.81 6408.52,6813.11 6406.72,6811.14 6404.91,6858.35 6406.77,6856.53 6408.98,6853.98 6411.51,6851 6414.29,6847.9 6417.27,6844.96 6418.83,6843.65 6420.41,6842.49 6422.03,6841.52 6423.66,6840.79 6425.31,6840.32
  region net B_SINGAL1: 6342.12,7025.78 6342.12,7035.78 6343.77,7035.95 6345.42,7036.43 6347.06,7037.18 6348.68,7038.16 6350.27,7039.34 6351.83,7040.67 6354.83,7043.66 6357.61,7046.84 6360.14,7049.89 6362.34,7052.51 6364.17,7054.41 6364.17,7007.16 6362.34,7009.06 6360.14,7011.68 6357.61,7014.73 6354.83,7017.91 6351.83,7020.9 6350.27,7022.23 6348.68,7023.41 6347.06,7024.39 6345.42,7025.14 6343.77,7025.62
  region net BO1: 6420.17,7340.15 6433.82,7330.15 6432.15,7329.98 6430.47,7329.48 6428.78,7328.69 6427.1,7327.64 6425.44,7326.39 6423.81,7324.96 6420.68,7321.73 6417.82,7318.27 6415.32,7314.86 6411.77,7309.46 6398.12,7354.69 6400.08,7353.43 6402.35,7351.49 6407.64,7346.6 6410.58,7344.17 6413.68,7342.12 6415.27,7341.31 6416.88,7340.69 6418.52,7340.29
  region net VCC+5V: 6340.11,6930.15 6344.29,6940.15 6345.95,6940.32 6347.59,6940.77 6349.21,6941.49 6350.82,6942.43 6353.95,6944.84 6356.92,6947.69 6362.22,6953.58 6364.45,6956.02 6366.34,6957.74 6362.16,6910.68 6360.41,6912.74 6358.24,6915.52 6355.73,6918.72 6352.92,6922.02 6349.89,6925.12 6348.32,6926.5 6346.71,6927.71 6345.07,6928.72 6343.42,6929.49 6341.77,6929.98
  region net VCC+5V: 6771.72,6648.79 ccw(c6742.93,6677.57) 6782.93,6670 6805,6675 6817.07,6670 ccw(c6857.07,6577.57) 6785.86,6648.79
  region net VCC+12V: 6612.5,7255 6612.93,7115.61 6775.91,7010.91 cw(c6843.9,7078.9) 6749.56,7097.5 6749.56,7142.5 cw(c6802.51,7277.5) 6657.5,7277.5
Bottom Layer:
  region net VCC+12V: 7927.5,7187.5 7927.5,7142.5 ccw(c7927.5,6835) 7860,7135 7860,7195 ccw(c7927.5,7495)
  region net VCC+3.3V: 7750,7138.07 7740,7115.57 7739.84,7117.17 7739.38,7118.8 7738.66,7120.47 7737.71,7122.13 7736.56,7123.79 7735.24,7125.42 7732.26,7128.53 7729.02,7131.33 7725.79,7133.69 7722.84,7135.48 7720.44,7136.57 7759.41,7159.07 7758.74,7157.21 7757.55,7155.06 7754.36,7150.02 7752.74,7147.21 7751.34,7144.26 7750.37,7141.19 7750.1,7139.64
  region net B_SINGAL2: 7635,4617.88 7645,4617.88 7645.17,4616.23 7645.65,4614.58 7646.39,4612.94 7647.37,4611.32 7648.55,4609.73 7649.89,4608.17 7652.88,4605.17 7656.05,4602.39 7659.1,4599.86 7661.73,4597.66 7663.62,4595.83 7616.38,4595.83 7618.28,4597.66 7620.9,4599.86 7623.95,4602.39 7627.12,4605.17 7630.12,4608.17 7631.45,4609.73 7632.63,4611.32 7633.61,4612.94 7634.36,4614.58 7634.83,4616.23
  region net A_SINGAL1: 7242.5,5130.31 7232.5,5134.06 7232.34,5135.71 7231.88,5137.36 7231.16,5138.99 7230.21,5140.59 7227.79,5143.72 7224.92,5146.7 7219,5152 7216.53,5154.23 7214.8,5156.11 7261.89,5152.36 7259.85,5150.6 7257.08,5148.43 7253.9,5145.91 7250.61,5143.11 7247.52,5140.09 7246.15,5138.51 7244.94,5136.9 7243.93,5135.27 7243.16,5133.62 7242.67,5131.97
  region net A_SINGAL2: 7166.79,5208.86 7173.86,5201.79 7172.81,5200.5 7171.98,5199 7171.35,5197.31 7170.9,5195.47 7170.61,5193.51 7170.45,5191.47 7170.44,5187.23 7170.72,5183.01 7171.09,5179.08 7171.39,5175.66 7171.44,5173.03 7138.03,5206.44 7140.66,5206.39 7144.08,5206.09 7148.02,5205.72 7152.23,5205.44 7156.47,5205.45 7158.51,5205.6 7160.47,5205.9 7162.31,5206.35 7164,5206.98 7165.5,5207.81
  region net VCC+3.3V: 6535,5217.88 6545,5217.88 6545.17,5216.23 6545.65,5214.58 6546.39,5212.94 6547.37,5211.32 6548.55,5209.73 6549.89,5208.17 6552.88,5205.17 6556.05,5202.39 6559.1,5199.86 6561.73,5197.66 6563.62,5195.83 6516.38,5195.83 6518.28,5197.66 6520.9,5199.86 6523.95,5202.39 6527.12,5205.17 6530.12,5208.17 6531.45,5209.73 6532.63,5211.32 6533.61,5212.94 6534.36,5214.58 6534.83,5216.23
  region net VCC+12V: 6181.24,6698.4 6181.24,6653.4 6178.54,6653.32 6175.86,6653.08 6170.57,6652.23 6165.46,6651.03 6160.6,6649.65 6151.94,6647.08 6148.3,6646.23 6145.24,6645.9 6145.24,6705.9 6148.3,6705.58 6151.94,6704.73 6160.6,6702.15 6165.46,6700.78 6170.57,6699.58 6175.86,6698.73 6178.54,6698.49
  region net GND: 6186.08,6273.82 6186.08,6263.82 6184.51,6263.66 6182.94,6263.22 6181.38,6262.51 6179.83,6261.59 6176.83,6259.24 6173.97,6256.43 6171.31,6253.45 6168.91,6250.58 6166.82,6248.11 6165.08,6246.32 6165.08,6291.32 6166.82,6289.53 6168.91,6287.06 6171.31,6284.19 6173.97,6281.21 6176.83,6278.4 6179.83,6276.04 6181.38,6275.12 6182.94,6274.42 6184.51,6273.98
  region net GND: 6345,6046.56 6355,6054.06 6355.19,6052.3 6355.72,6050.53 6356.57,6048.77 6357.68,6047.02 6359.01,6045.3 6360.52,6043.61 6363.93,6040.37 6367.56,6037.37 6371.09,6034.7 6376.51,6030.64 6326.88,6023.14 6328.58,6025.19 6331.06,6027.58 6337.14,6033.2 6340.11,6036.34 6341.44,6037.98 6342.62,6039.65 6343.6,6041.35 6344.35,6043.07 6344.83,6044.81
  region net VCC+12V: 7677.88,7567.5 7677.88,7522.5 7671.18,7522.74 7664.79,7523.03 7661.94,7523.02 7659.43,7522.79 7657.37,7522.26 7656.53,7521.87 7655.83,7521.38 7655.83,7568.62 7656.53,7568.13 7657.37,7567.74 7659.43,7567.21 7661.94,7566.98 7664.79,7566.97 7671.18,7567.26
  region net A_SINGAL1: 8107.88,7149.22 8107.88,7139.22 8106.23,7139.05 8104.58,7138.57 8102.94,7137.82 8101.32,7136.84 8099.73,7135.66 8098.17,7134.33 8095.17,7131.34 8092.39,7128.16 8089.86,7125.11 8087.66,7122.49 8085.83,7120.59 8085.83,7167.84 8087.66,7165.94 8089.86,7163.32 8092.39,7160.27 8095.17,7157.09 8098.17,7154.1 8099.73,7152.77 8101.32,7151.59 8102.94,7150.61 8104.58,7149.86 8106.23,7149.38
  region net A_SINGAL2: 8107.88,7050.8 8107.88,7040.8 8106.23,7040.63 8104.58,7040.15 8102.94,7039.4 8101.32,7038.42 8099.73,7037.24 8098.17,7035.91 8095.17,7032.92 8092.39,7029.74 8089.86,7026.69 8087.66,7024.07 8085.83,7022.17 8085.83,7069.42 8087.66,7067.52 8089.86,7064.9 8092.39,7061.85 8095.17,7058.67 8098.17,7055.68 8099.73,7054.35 8101.32,7053.17 8102.94,7052.19 8104.58,7051.44 8106.23,7050.96
  region net B_SINGAL2: 6341.53,7125 6342.72,7135 6344.38,7135.17 6346.02,7135.64 6347.66,7136.38 6349.27,7137.35 6350.86,7138.51 6352.42,7139.83 6355.4,7142.79 6358.19,7145.92 6360.71,7148.92 6362.92,7151.5 6364.77,7153.35 6363.58,7106.12 6361.77,7108.06 6359.58,7110.73 6357.06,7113.83 6354.27,7117.04 6351.26,7120.07 6349.69,7121.42 6348.1,7122.6 6346.48,7123.6 6344.84,7124.35 6343.18,7124.83
  region net VCC+12V: 7830,7142.5 cw(c7830,6961.16) 7949.56,7097.5 7972.06,7167.19 7949.56,7232.5 cw(c7830,7368.84) 7830,7187.5

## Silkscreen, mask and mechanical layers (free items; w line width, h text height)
Top Silkscreen Layer:
  text "VCC" at 6910,7590 h60
  text "GND" at 7100,7590 h60
  text "1000uf" at 7545,7415 h60
  text "AO2" at 7895,7305 h60
  text "BO1" at 6445,7300 h60
  text "VCC" at 7890,7215 h60
  text "GND" at 6445,7200 h60
  text "A_SINGAL1" at 7686.4,7110 h60
  text "B_SINGAL2" at 6430,7100 h60
  text "10uf" at 6765,7065 h60
  text "VCC" at 7670,7065 h60
  text "VM" at 7790,7065 h60
  text "A_SINGAL2" at 7690,7010 h60
  text "B_SINGAL1" at 6445,7005 h60
  text "GND" at 7900,6915 h60
  text "VCC" at 6445,6910 h60
  text "AO1" at 7905,6825 h60
  text "BO2" at 6445,6810 h60
  text "GND" at 8075,6690 h60
  text "GND" at 8195,6690 h60
  text "LED" at 7940,6585 h60
  text "RX" at 8215,6535 h60
  text "TX" at 8215,6430 h60
  text "MP1584" at 6405,6385 h60
  text "R103" at 8060,6270 h60
  text "100nf" at 7290,6065 h60
  text "100uf" at 7040,6025 h60
  text "100nf" at 6505,5810 h60
  text "100uf" at 6186.56,5780 h60
  text "R104" at 6875,5510 h60
  text "ros2_usv_platform / Author: CNXWZY / License: CC BY-NC-SA 4.0" at 6700,5335 h120
  text "VCC" at 6480,5215 h60
  text "GND" at 6280,5080 h60
  text "GND" at 6400,5080 h60
  text "GND" at 8085,4480 h60
  text "VCC" at 8210,4480 h60
  text "100nf" at 7840,4325 h60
